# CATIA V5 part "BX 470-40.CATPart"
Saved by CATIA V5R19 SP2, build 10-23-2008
Part number: BX 470-40
Bounding box of the stored display mesh (mm): x -37.351 to 37.351, y -37.351 to 37.351, z 0 to 200
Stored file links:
  C:\Users\Bora\Desktop\3D Katı model\BX serisi\BX 470\BX 470-40.CATPart
  C:\Program Files\Dassault Systemes\B19\intel_a\reffiles\standard\MetricThickPitch.txt
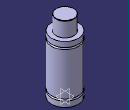
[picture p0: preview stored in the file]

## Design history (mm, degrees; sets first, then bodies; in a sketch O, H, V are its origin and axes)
Body1 (main body)
  Sketch1 on yz-plane, origin (0, 0, 0), H (0, 1, 0), V (0, 0, 1)
    point P2 (37.5, 15.5)
    line L1 (37.5, 15.5) -> (37.5, 0)
    point P3 (37.5, 20.5)
    point P4 (37.5, 139.5)
    line L2 (37.5, 139.5) -> (37.5, 20.5)
    point P6 (25, 199)
    arc A1 centre (24, 199) radius 1 from (25, 199) to (24, 200) ccw
    point P8 (25, 199)
    line L3 (25, 199) -> (25, 159)
    point P9 (37.5, 144.5)
    line L4 (37.5, 159) -> (37.5, 144.5)
    point P11 (37.5, 15.5)
    point P12 (37.5, 20.5)
    arc A2 centre (37.5, 18) radius 2.5 from (37.5, 20.5) to (37.5, 15.5) ccw
    point P13 (37.5, 139.5)
    point P14 (37.5, 144.5)
    arc A3 centre (37.5, 142) radius 2.5 from (37.5, 144.5) to (37.5, 139.5) ccw
    line L5 (24, 200) -> (0, 200)
    line L6 (25, 159) -> (37.5, 159)
    line L7 (37.5, 0) -> (0, 0)
    tangency: L5 A1
    horizontal: L6 H, L7 H
    coincidence: P2 P11, P3 P12, P4 P13, P6 P8, P9 P14
  Shaft1: profile Sketch1, axis Sketch1.V, angle 360
  Sketch2 on face of Shaft1 from Sketch1.L7, origin (0, 0, 0), H (1, 0, 0), V (0, -1, 0)
    point P1 (20, 0)
    distance P1 V = 20
  Hole1: placed by Sketch2, at (20, 0, 0) direction (0, 0, 1), diameter 6.647, depth 7, threaded "M8", thread diameter 8, thread depth 7, pitch 1.25
  CircPattern1: of Hole1, instances 4, angular step 90, axis from xy-plane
